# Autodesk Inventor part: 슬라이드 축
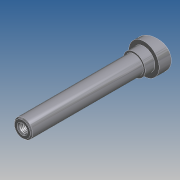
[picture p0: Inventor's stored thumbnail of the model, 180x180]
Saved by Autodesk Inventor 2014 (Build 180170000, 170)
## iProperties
Company: 한국ATC센터
Created: 2012-05
Part Number: 슬라이드 축
Document SubType Name: 모델링
Designer: KYOUNG IL JANG
Mass: 169.556 g
Surface Area: 67.5855 cm^2
Volume: 21.572 cm^3
Density: 7.86 g/cm^3
Material: 강, 연강
Appearance: 강철
변환 표준: STEP AP214IS
파일 이름: C:\Users\SeoGD\Desktop\?쒗뿕\異?stp
전처리기: Build: 253, Release: 2010 SP1 - Date: Wed 07/29/2009
전송 단위: 밀리미터
불확실성: 0.01
Author: KYOUNG IL JANG
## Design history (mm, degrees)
sketch "스케치1"
  geometry: L1 (0, 100)-(7.5, 100); L2 (7.5, 100)-(7.5, 0); L3 (7.5, 0)-(12.5, 0); L4 (12.5, 0)-(12.5, -17); L5 (12.5, -17)-(0, -17); L6 (0, -17)-(0, 100); 1 further point
  constraints: 12 end point, 2 parallel, 2 point on line, 1 perpendicular, 1 vertical
  dimensions: "d0" = 100 distance from line of L1 point (0, 0); "d1" = 15 diameter of L2 L6; "d2" = 25 diameter of L4 L6; "d3" = 17 distance of L3.end L4.end
revolve "회전1" sketch "스케치1" stored, may be unused: angle "d4" = 90 deg
sketch "스케치2"
  geometry: L1 (12.5, 0)-(12.5, -17) reference; L2 (-12.5, -17)-(12.5, -17) reference; L3 (-12.5, 0)-(-12.5, -17) reference; L4 (12.5, -5)-(-12.5, -11.699); L5 (-12.5, 0)-(12.5, 0) reference; 1 further point
  constraints: 2 end point, 2 point on line
  dimensions: "d5" = 75 deg angle of L1 L4; "d6" = 5 distance from line of L4.start L5
extrude "돌출1" cut sketch "스케치2" stored distance "d7" = 10; taper "d8" = 0 deg
chamfer "모따기1" distance "d9" = 1; stored, may be unused: second distance "d10" = 2, angle "d11" = 45 deg
fillet "모깎기1" dims "d12" = 0.5
hole "구멍1" diameter "d15" = 6.647; stored, may be unused: countersink angle "d19" = 90 deg, drill point angle "d21" = 118 deg; dims "d13" = 10, "d14" = 10, "d16" = 17, "d17" = 4, "d18" = 2, "d20" = 20
chamfer "모따기2" distance "d22" = 1; stored, may be unused: second distance "d23" = 2, angle "d24" = 45 deg
sketch "스케치3"
  geometry: C1 r 9 at (0, 0); 1 further point
  constraints: 1 centre point, 1 coincident
  dimensions: "d25" = 18 diameter of C1
extrude "돌출2" join sketch "스케치3" distance "d26" = 8; taper "d27" = 0 deg
node "솔리드1"
node "솔리드 본체"
node "곡면 본체"
node "솔리드2"
